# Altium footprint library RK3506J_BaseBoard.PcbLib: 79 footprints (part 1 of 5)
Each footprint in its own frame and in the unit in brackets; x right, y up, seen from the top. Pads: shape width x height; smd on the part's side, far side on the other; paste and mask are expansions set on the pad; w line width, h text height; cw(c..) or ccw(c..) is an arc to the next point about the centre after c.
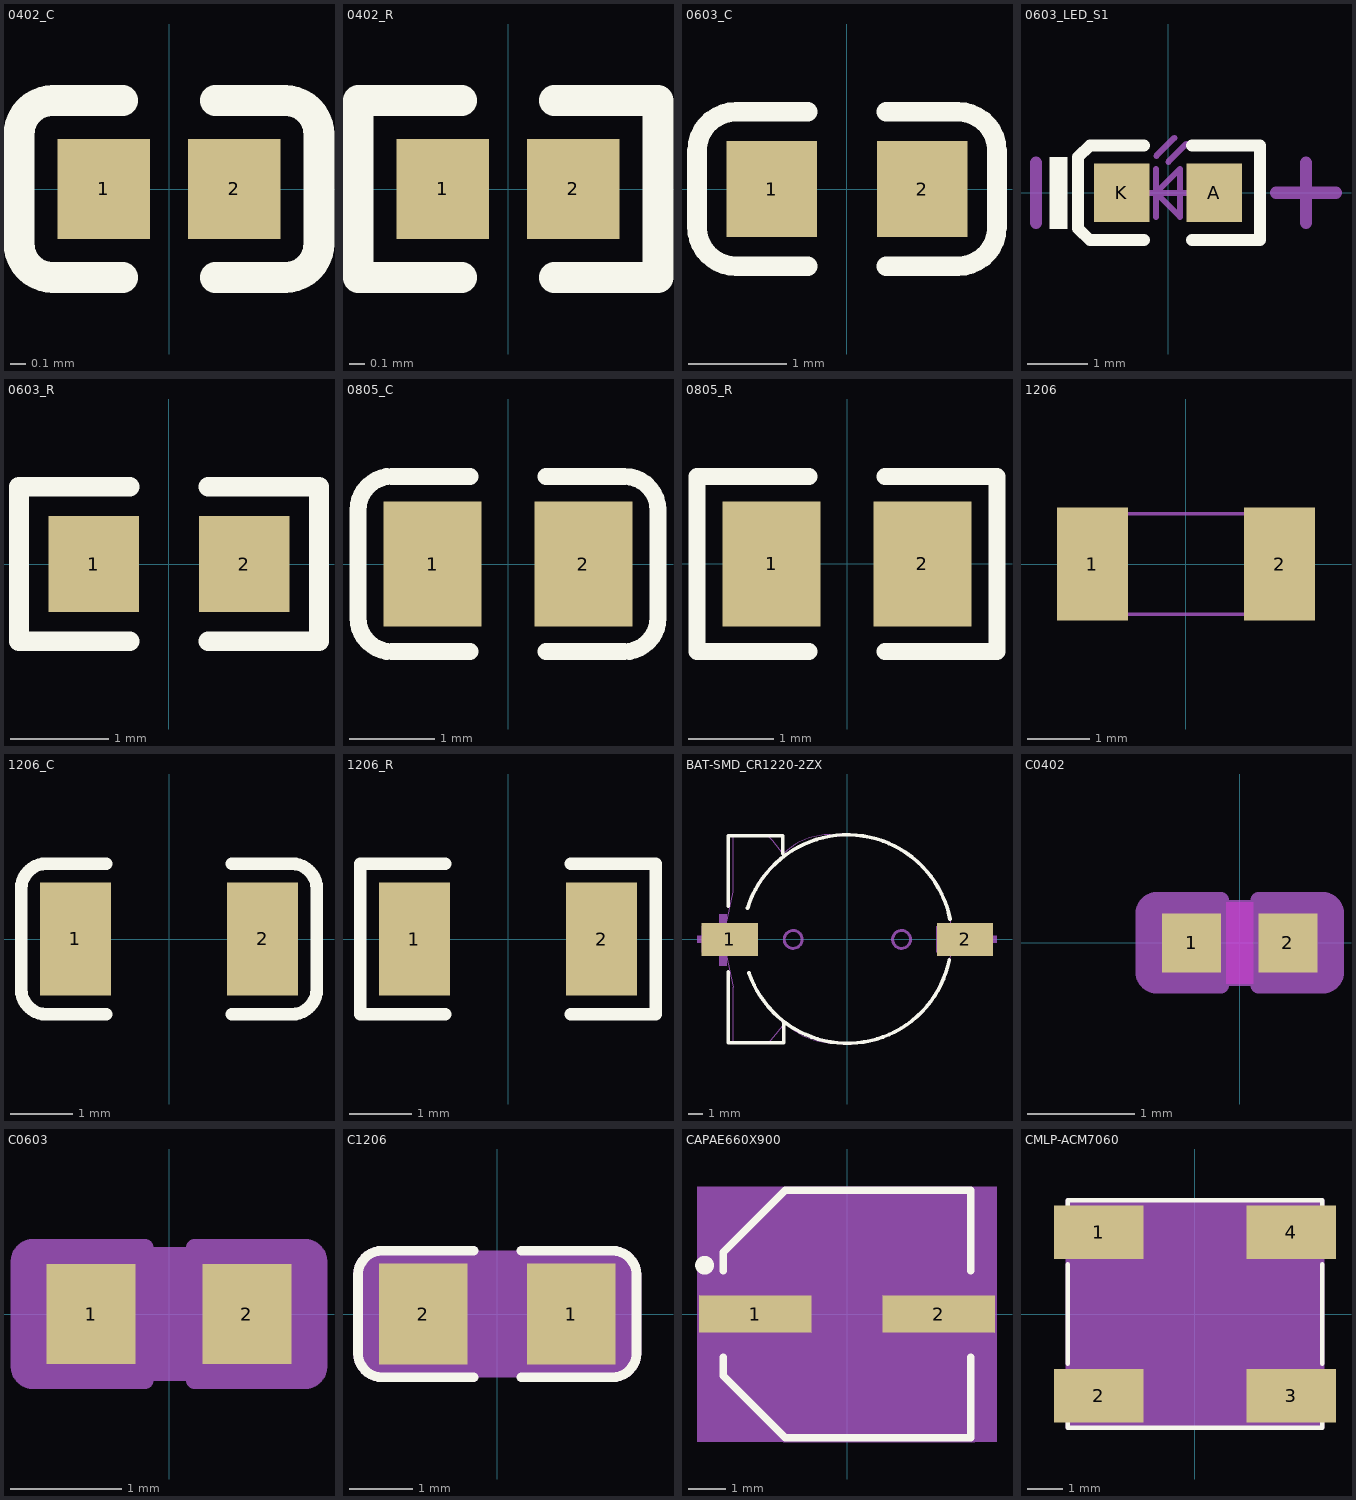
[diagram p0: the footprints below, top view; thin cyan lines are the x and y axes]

## 0402_C [mm]
pads (2):
  rect 0.6x0.65 smd mask+0.051: 1(-0.425,0) 2(0.425,0)
Top Overlay:
  lines w0.2: -0.755,-0.575 cw(c-0.755,-0.355) -0.975,-0.355 -0.975,0.355 cw(c-0.755,0.355) -0.755,0.575 ; -0.75,-0.575 -0.3,-0.575 ; -0.75,0.575 -0.3,0.575 ; 0.3,-0.575 0.75,-0.575 ; 0.3,0.575 0.75,0.575 ; 0.755,-0.575 ccw(c0.755,-0.355) 0.975,-0.355 0.975,0.355 ccw(c0.755,0.355) 0.755,0.575
3D body "0402 SMD Capacitor.step": height 0.2, standoff 0, extent -0.483,-0.3 0.517,0.3

## 0402_R [mm]
pads (2):
  rect 0.6x0.65 smd mask+0.051: 1(-0.425,0) 2(0.425,0)
Top Overlay:
  lines w0.2: -0.3,-0.575 -0.975,-0.575 -0.975,0.575 -0.3,0.575 ; 0.3,-0.575 0.975,-0.575 0.975,0.575 0.3,0.575
3D body "User Library-RES_1005-0402.STEP": height 0.41, standoff 0, extent -0.575,-0.275 0.575,0.275

## 0603_C [mm]
pads (2):
  rect 0.93x0.98 smd: 1(-0.77,0) 2(0.77,0)
Top Overlay:
  lines w0.2: -0.4,-0.79 -1.135,-0.79 cw(c-1.135,-0.39) -1.535,-0.39 -1.535,0.39 cw(c-1.135,0.39) -1.135,0.79 -0.4,0.79 ; 0.4,-0.79 1.135,-0.79 ccw(c1.135,-0.39) 1.535,-0.39 1.535,0.39 ccw(c1.135,0.39) 1.135,0.79 0.4,0.79
3D body "User Library-0603 SMD Capacitor.STEP": height 0.3, standoff 0, extent -0.8,-0.4 0.8,0.4

## 0603_LED_S1 [mm]
pads (2):
  rect 0.93x0.98 smd: A(0.77,0) K(-0.77,0)
Top Overlay:
  rectangle: -1.975,-0.6 -1.675,0.6
  lines w0.2: -0.4,-0.79 -1.3,-0.79 -1.5,-0.597 -1.5,0.597 -1.3,0.79 -0.4,0.79 ; 0.4,-0.79 1.535,-0.79 1.535,0.79 0.4,0.79
Mechanical 13:
  lines w0.1: -0.4,0 0.4,0 ; -0.2,-0.4 -0.2,0.4 ; -0.195,0.617 0.105,0.917 ; 0.005,0.517 0.305,0.817 ; -0.2,0 0.2,-0.4 0.2,0.4 -0.2,0
Mechanical 15:
  lines w0.203: -2.2,-0.5 -2.2,0.5 ; 1.8,0 2.8,0 ; 2.3,-0.5 2.3,0.5
3D body "User Library-LED_0603_R.STEP": height 0.6, standoff 0, extent -0.8,-0.4 0.8,0.4

## 0603_R [mm]
pads (2):
  rect 0.93x0.98 smd: 1(-0.77,0) 2(0.77,0)
Top Overlay:
  lines w0.2: -0.4,-0.79 -1.535,-0.79 -1.535,0.79 -0.4,0.79 ; 0.4,-0.79 1.535,-0.79 1.535,0.79 0.4,0.79
3D body "User Library-RES_1609-0603.STEP": height 0.56, standoff 0, extent -0.85,-0.4 0.85,0.4

## 0805_C [mm]
pads (2):
  rect 1.16x1.47 smd: 1(-0.89,0) 2(0.89,0)
Top Overlay:
  lines w0.2: -0.45,-1.035 -1.37,-1.035 cw(c-1.37,-0.635) -1.77,-0.635 -1.77,0.635 cw(c-1.37,0.635) -1.37,1.035 -0.45,1.035 ; 0.45,-1.035 1.37,-1.035 ccw(c1.37,-0.635) 1.77,-0.635 1.77,0.635 ccw(c1.37,0.635) 1.37,1.035 0.45,1.035
3D body "User Library-0805 SMD Capacitor.STEP": height 0.77, standoff -0.01, extent -1,-0.625 1.001,0.625

## 0805_R [mm]
pads (2):
  rect 1.16x1.47 smd: 1(-0.89,0) 2(0.89,0)
Top Overlay:
  lines w0.2: -0.45,-1.035 -1.77,-1.035 -1.77,1.035 -0.45,1.035 ; 0.45,-1.035 1.77,-1.035 1.77,1.035 0.45,1.035
3D body "User Library-R_0805.STEP": height 0.49, standoff -0.01, extent -0.997,-0.625 1.003,0.625

## 1206 [mm]
pads (2):
  rect 1.13x1.8 smd: 1(-1.49,0) 2(1.49,0)
Mechanical 13:
  lines w0.05: -1.6,-0.8 1.6,-0.8 1.6,0.8 -1.6,0.8 -1.6,-0.8

## 1206_C [mm]
pads (2):
  rect 1.13x1.8 smd: 1(-1.49,0) 2(1.49,0)
Top Overlay:
  lines w0.2: -1,-1.2 -1.955,-1.2 cw(c-1.955,-0.8) -2.355,-0.8 -2.355,0.8 cw(c-1.955,0.8) -1.955,1.2 -1,1.2 ; 1,-1.2 1.955,-1.2 ccw(c1.955,-0.8) 2.355,-0.8 2.355,0.8 ccw(c1.955,0.8) 1.955,1.2 1,1.2
3D body "C1206.STEP": height 1, standoff 0, extent -1.602,-0.813 1.598,0.787

## 1206_R [mm]
pads (2):
  rect 1.13x1.8 smd: 1(-1.49,0) 2(1.49,0)
Top Overlay:
  lines w0.2: -1,-1.2 -2.355,-1.2 -2.355,1.2 -1,1.2 ; 1,-1.2 2.355,-1.2 2.355,1.2 1,1.2
3D body "User Library-RES_3216-1206.STEP": height 0.85, standoff 0, extent -1.7,-0.864 1.65,0.866

## BAT-SMD_CR1220-2ZX [mm]
pads (2):
  rect 3.9x2.3 smd paste+0 mask+0.051: 1(-8.15,0) 2(8.15,0)
Top Overlay:
  lines w0.254: -8.24,-2.26 -8.24,-7.15 -4.4,-7.15 -4.4,-5.706 -4.378,-5.706 ; -8.24,2.3 -8.24,7.17 -5.51,7.17 -4.47,7.17 -4.47,5.95 ; -6.911,2.175 cw(c0,0) 7.109,1.399 ; -6.815,-2.297 ccw(c0,0) 7.051,-1.418
Mechanical 1:
  circle w0.203: c-3.75,0 r0.62
  circle w0.203: c3.75,0 r0.62
Top 3D Body:
  drawing of 7 lines, arcs and shapes, not listed
Mechanical 15:
  region: 6.17,0.9 9.67,0.9 9.67,-0.9 6.17,-0.9
  region: -6.57,-0.9 -10.07,-0.9 -10.07,0.9 -6.57,0.9
  lines w0.051: -8.382,-1.016 -8.38,-1.07 -7.89,-3.3 -7.89,-7.15 -5.48,-7.15 -5.26,-6.93 -4.315,-5.754 ccw(c-0.843,-2.281) -0.843,-7.192 0,-7.192 0.053,-7.192 ccw(c0.053,0) 7.245,0 7.245,0.08 ccw(c0.081,0.08) 0.081,7.245 -1.232,7.245 ccw(c-1.232,2.722) -4.43,5.92 -4.47,5.92 -5.2,6.88 -5.47,7.15 -7.89,7.15 -7.89,3.3 -8.382,1.016 -8.382,-1.016

## C0402 [mm]
pads (2):
  rect 0.55x0.55 smd: 1(-0.45,0) 2(0.45,0)
Top Layer keep-out:
  region: -0.127,-0.381 -0.127,0.381 0.127,0.381 0.127,-0.381
Top Overlay:
Top 3D Body:
  region: -0.773,-0.4 -0.784,-0.4 -0.795,-0.398 -0.806,-0.396 -0.816,-0.392 -0.827,-0.388 -0.836,-0.383 -0.846,-0.377 -0.855,-0.37 -0.863,-0.363 -0.87,-0.355 -0.877,-0.346 -0.883,-0.337 -0.888,-0.327 -0.892,-0.317 -0.896,-0.306 -0.898,-0.295 -0.899,-0.284 -0.9,-0.273 -0.9,0.273 -0.899,0.284 -0.898,0.295 -0.896,0.306 -0.892,0.317 -0.888,0.327 -0.883,0.337 -0.877,0.346 -0.87,0.355 -0.863,0.363 -0.855,0.37 -0.846,0.377 -0.836,0.383 -0.827,0.388 -0.816,0.392 -0.806,0.396 -0.795,0.398 -0.784,0.4 -0.773,0.4 0.773,0.4 0.784,0.4 0.795,0.398 0.806,0.396 0.816,0.393 0.827,0.388 0.836,0.383 0.846,0.377 0.855,0.37 0.863,0.363 0.87,0.355 0.877,0.346 0.883,0.337 0.888,0.327 0.892,0.317 0.896,0.306 0.898,0.295 0.899,0.284 0.9,0.273 0.9,-0.273 0.899,-0.284 0.898,-0.295 0.896,-0.306 0.892,-0.317 0.888,-0.327 0.883,-0.337 0.877,-0.346 0.87,-0.355 0.863,-0.363 0.855,-0.37 0.846,-0.377 0.836,-0.383 0.827,-0.388 0.816,-0.392 0.806,-0.396 0.795,-0.398 0.784,-0.4 0.773,-0.4
Top Assembly:
  lines w0.15: -0.175,-0.4 -0.773,-0.4 cw(c-0.773,-0.273) -0.9,-0.273 -0.9,0.273 cw(c-0.773,0.273) -0.773,0.4 -0.175,0.4 ; 0.175,-0.4 0.773,-0.4 ccw(c0.773,-0.273) 0.9,-0.273 0.9,0.273 ccw(c0.773,0.273) 0.773,0.4 0.175,0.4
Mechanical 15:
  text "1" at -0.45,0.254 h0.76
  text "2" at 0.45,0.254 h0.76
3D body: height 3.81, standoff 0, extent -0.9,-0.4 0.9,0.4

## C0603 [mm]
pads (2):
  rect 0.8x0.9 smd: 1(-0.7,0) 2(0.7,0)
Top 3D Body:
  region: -1.222,-0.599 -1.233,-0.599 -1.244,-0.598 -1.255,-0.595 -1.265,-0.592 -1.275,-0.588 -1.285,-0.582 -1.295,-0.576 -1.303,-0.57 -1.312,-0.562 -1.319,-0.554 -1.326,-0.545 -1.332,-0.536 -1.337,-0.526 -1.341,-0.516 -1.344,-0.505 -1.347,-0.494 -1.348,-0.484 -1.349,-0.472 -1.349,0.472 -1.348,0.484 -1.347,0.494 -1.344,0.505 -1.341,0.516 -1.337,0.526 -1.332,0.536 -1.326,0.545 -1.319,0.554 -1.312,0.562 -1.303,0.57 -1.295,0.576 -1.285,0.582 -1.275,0.588 -1.265,0.592 -1.255,0.595 -1.244,0.598 -1.233,0.599 -1.222,0.599 1.222,0.599 1.233,0.599 1.244,0.598 1.255,0.595 1.265,0.592 1.275,0.588 1.285,0.582 1.295,0.576 1.303,0.57 1.312,0.562 1.319,0.554 1.326,0.545 1.332,0.536 1.337,0.526 1.341,0.516 1.344,0.505 1.347,0.494 1.348,0.484 1.349,0.472 1.349,-0.472 1.348,-0.484 1.347,-0.494 1.344,-0.505 1.341,-0.516 1.337,-0.526 1.332,-0.536 1.326,-0.545 1.319,-0.554 1.312,-0.562 1.303,-0.57 1.295,-0.576 1.285,-0.582 1.275,-0.588 1.265,-0.592 1.255,-0.595 1.244,-0.598 1.233,-0.599 1.222,-0.599
Top Assembly:
  lines w0.15: -0.212,-0.599 -1.222,-0.599 cw(c-1.222,-0.472) -1.349,-0.472 -1.349,0.472 cw(c-1.222,0.472) -1.222,0.599 -0.212,0.599 ; 0.229,-0.599 1.222,-0.599 ccw(c1.222,-0.472) 1.349,-0.472 1.349,0.472 ccw(c1.222,0.472) 1.222,0.599 0.229,0.599
  text "22uF" at -1.524,0 h0.64
Mechanical 15:
  text "1" at -0.7,0.254 h0.64
  text "2" at 0.7,0.254 h0.64
3D body: height 3.81, standoff 0, extent -1.349,-0.599 1.349,0.599

## C1206 [mm]
pads (2):
  rect 1.4x1.6 smd: 1(1.168,0) 2(-1.168,0)
Top Overlay:
  lines w0.152: -0.375,-1 -1.819,-1 cw(c-1.819,-0.619) -2.2,-0.619 -2.2,0.619 cw(c-1.819,0.619) -1.819,1 -0.375,1 ; 0.379,-1 1.819,-1 ccw(c1.819,-0.619) 2.2,-0.619 2.2,0.619 ccw(c1.819,0.619) 1.819,1 0.379,1
Top 3D Body:
  region: 1.819,1 1.852,0.999 1.885,0.994 1.918,0.987 1.949,0.977 1.98,0.964 2.009,0.949 2.037,0.931 2.064,0.911 2.088,0.888 2.111,0.864 2.131,0.838 2.149,0.809 2.164,0.78 2.177,0.749 2.187,0.718 2.194,0.685 2.198,0.652 2.2,0.619 2.2,-0.619 2.198,-0.652 2.194,-0.685 2.187,-0.718 2.177,-0.749 2.164,-0.78 2.149,-0.809 2.131,-0.838 2.111,-0.864 2.088,-0.888 2.064,-0.911 2.037,-0.931 2.009,-0.949 1.98,-0.964 1.949,-0.977 1.918,-0.987 1.885,-0.994 1.852,-0.999 1.819,-1 -1.819,-1 -1.852,-0.999 -1.885,-0.994 -1.918,-0.987 -1.949,-0.977 -1.98,-0.964 -2.009,-0.949 -2.037,-0.931 -2.064,-0.911 -2.088,-0.888 -2.111,-0.864 -2.131,-0.838 -2.149,-0.809 -2.164,-0.78 -2.177,-0.749 -2.187,-0.718 -2.194,-0.685 -2.198,-0.652 -2.2,-0.619 -2.2,0.619 -2.198,0.652 -2.194,0.685 -2.187,0.718 -2.177,0.749 -2.164,0.78 -2.149,0.809 -2.131,0.838 -2.111,0.864 -2.088,0.888 -2.064,0.911 -2.037,0.931 -2.009,0.949 -1.98,0.964 -1.949,0.977 -1.918,0.987 -1.885,0.994 -1.852,0.999 -1.819,1
Top Assembly:
  lines w0.152: -0.375,-1 -1.819,-1 cw(c-1.819,-0.619) -2.2,-0.619 -2.2,0.619 cw(c-1.819,0.619) -1.819,1 -0.375,1 ; 0.379,-1 1.819,-1 ccw(c1.819,-0.619) 2.2,-0.619 2.2,0.619 ccw(c1.819,0.619) 1.819,1 0.379,1
  text "1nF" at 1.778,0.127 h0.25
Mechanical 15:
  text "1" at 1.168,0 h0.25
  text "2" at -1.168,0 h0.25
3D body: height 3.81, standoff 0, extent -2.2,-1 2.2,1

## CAPAE660X900 [mm]
pads (2):
  rect 3x1 smd: 1(-2.45,0) 2(2.45,0)
Top Overlay:
  circle w0.25: c-3.8,1.3 r0.125
  lines w0.2: -3.3,-1.15 -3.3,-1.65 -1.65,-3.3 3.3,-3.3 3.3,-1.15 ; -3.3,1.15 -3.3,1.65 -1.65,3.3 3.3,3.3 3.3,1.15
Top 3D Body:
  circle w0.05: c0,0 r0.35
  region: 4,3.4 4,-3.4 -4,-3.4 -4,3.4
  lines w0.05: -0.5,0 0.5,0 ; 0,-0.5 0,0.5
Top Assembly:
  lines w0.1: -3.3,-1.65 -3.3,1.65 -1.65,3.3 3.3,3.3 3.3,-3.3 -1.65,-3.3 -3.3,-1.65
Top Component Outline:
  lines w0.001: -3.4,-1.7 -3.4,1.7 -1.7,3.4 3.4,3.4 3.4,-3.4 -1.7,-3.4 -3.4,-1.7
Top Courtyard:
  dashed: 4,3.4 4,-3.4 -4,-3.4 -4,3.4
Mechanical 15:
  text "1" at -2.196,0 h0.76
  text "2" at 2.704,0 h0.76
3D body: height 3.81, standoff 0, extent -4,-3.4 4,3.4

## CMLP-ACM7060 [mil]
pads (4):
  rect 98.43x59.06 smd: 1(-106,90) 2(-106,-90) 3(106,-90) 4(106,90)
Top Overlay:
  lines w5: -140,-120 -140,-125 140,-125 140,-120 ; -140,-55 -140,55 ; -140,120 -140,125 140,125 140,120 ; 140,-55 140,55
Top 3D Body:
  region: -140,125 -140,-125 140,-125 140,125
Top Assembly:
  lines w5: -140,-125 140,-125 140,125 -140,125 -140,-125
Mechanical 15:
  text "1" at -106,70 h30
  text "2" at -106,-110 h30
  text "3" at 106,-110 h30
  text "4" at 106,70 h30
3D body: height 150, standoff 0, extent -140,-125 140,125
